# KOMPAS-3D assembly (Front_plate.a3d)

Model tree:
1. X Axis
2. Y Axis
3. Z Axis
4. Origin
5. Linear Pattern:1  (labels: Instance ( 2, 1 );; Instance ( 3, 1 );; Instance ( 4, 1 );; Instance ( 5, 1 );)
     Included Angle = 90; N 2 = 1; Spacing 2 = 10; Orientation = 1

Expressions: (FP_W-(2*Delta)); (FP_W-(2*Delta))-100
Referenced files in D:\Documents and Settings\kashirsky\Рабочий стол\My sample\: skrzynia1.a3d|L, skrzynia1.a3d|H, skrzynia1.a3d|NR_Front, skrzynia1.a3d|Delta, Front_plate.m3d, rail3.m3d, Front_plate.a3d, Front_plate.spw, skrzynia1.a3d, skrzynia1.spw, Box.cdw
Referenced files in C:\Work\01 К О М П А С\Модели примеры\2009_04_For_Poland_AXAPACK\My sample\: skrzynia1.a3d
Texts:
  Plate 03
  Wood (15% moisture content)
  Three Point Plane
  Plane at Angle
  Line and Point Plane
  Axis through Two Vertices
  Axis of Feature
  Axis of Conical Surface
  Axis through Edge
  Trim by Surface
  Trim by Sketch
  Intersection Axis of Two Planes
  Two Line Plane
  Line and Face Plane
  Pattern by Sample
  Point in CM
  Feature with No History
  Linear Dimension from Line to Point
  Surface Finish Symbol
  Geometric Tolerance Symbol
  Leader #1
  Leader #2
  Leader #3
  Shape Deviations and Datum
  Node point number
  Mark of coordination axis
  Node point designation
  Mark/Reference designation with leader
  Mark/reference designation on line
  Mark/Reference designation without leader
  LR2
  Rail 03
  Instance ( 2, 1 );
  Instance ( 3, 1 );
  Instance ( 4, 1 );
  Instance ( 5, 1 );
